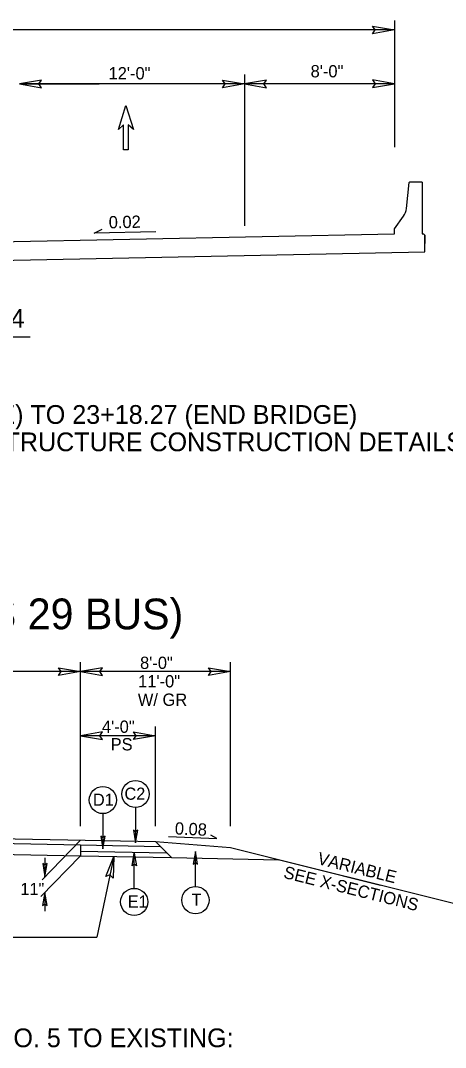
# Model space of a CAD drawing. Extents: x 1901582 to 1902252, y 193723 to 194156.
# Drawn here: x 1902055.4 to 1902078.1, y 193946 to 194000.8 of the extents above; entities that cross this region are included whole.
import ezdxf

# ---------------------------------------------------------------- set-up
doc = ezdxf.new("R2010")
doc.units = 0
for name, color, linetype in [('Old_Level_1', 7, 'Continuous'), ('Old_Level_11', 7, 'Continuous'), ('Old_Level_2', 7, 'Continuous'), ('Old_Level_20', 7, 'Continuous'), ('Prop Dimension', 7, 'Continuous'), ('Prop Dimension Text', 7, 'Continuous'), ('Typical Pavement Slope Information CELL', 7, 'Continuous'), ('Typical Terminator CELL', 7, 'Continuous'), ('Typical Text Centerline CELL', 7, 'Continuous')]:
    doc.layers.add(name, color=color, linetype=linetype)

# ---------------------------------------------------------------- blocks, each defined once
blk = doc.blocks.new('TERMINATOR')
at = {"layer": 'Typical Terminator CELL'}
blk.add_lwpolyline([(-0.469, 0.081), (0, 0), (-0.471, -0.083), (-0.411, 0)], close=True, dxfattribs=at)

msp = doc.modelspace()

# ---------------------------------------------------------------- linework, layer by layer
at = {"layer": 'Old_Level_1'}
for p, q in [((1902075.381, 194000.779), (1902075.381, 193994.021)), ((1902067.381, 193997.904), (1902067.381, 193989.821)), ((1902076.16, 193992.142), (1902076.196, 193992.179)), ((1902076.196, 193992.179), (1902076.826, 193992.179)), ((1902076.826, 193992.179), (1902076.859, 193992.146)), ((1902076.013, 193990.751), (1902076.16, 193992.142)), ((1902076.859, 193992.146), (1902076.859, 193989.398)), ((1902075.381, 193989.659), (1902075.861, 193990.344)), ((1902075.381, 193989.398), (1902075.381, 193989.659)), ((1902043.381, 193988.758), (1902075.381, 193989.398)), ((1902076.859, 193989.398), (1902076.924, 193989.398)), ((1902076.924, 193989.398), (1902076.989, 193989.333)), ((1902076.989, 193988.43), (1902076.989, 193989.333)), ((1902076.989, 193989.333), (1902076.989, 193988.876)), ((1902016.274, 193987.216), (1902076.989, 193988.43)), ((1902058.631, 193957.787), (1902058.631, 193966.537)), ((1902066.631, 193957.784), (1902066.631, 193966.537)), ((1902058.631, 193966.037), (1902046.631, 193966.037)), ((1902066.631, 193966.037), (1902058.631, 193966.037)), ((1902062.631, 193957.787), (1902062.631, 193963.118)), ((1902062.631, 193962.618), (1902058.631, 193962.618)), ((1902046.631, 193957.287), (1902062.631, 193956.967)), ((1902046.631, 193957.037), (1902058.631, 193956.797)), ((1902058.631, 193957.047), (1902056.583, 193954.931)), ((1902058.631, 193956.797), (1902058.631, 193956.213)), ((1902058.631, 193956.797), (1902062.886, 193956.712)), ((1902062.631, 193956.967), (1902063.482, 193956.116)), ((1902062.631, 193956.967), (1902066.631, 193956.647)), ((1902066.631, 193956.647), (1902074.631, 193954.647)), ((1902066.631, 193956.647), (1902078.874, 193953.586)), ((1902046.631, 193956.453), (1902058.631, 193956.213)), ((1902058.631, 193956.213), (1902056.525, 193954.037)), ((1902056.74, 193956.093), (1902056.74, 193955.093)), ((1902058.631, 193956.463), (1902063.227, 193956.372)), ((1902058.631, 193956.213), (1902063.482, 193956.116)), ((1902060.41, 193956.178), (1902059.508, 193951.867)), ((1902063.482, 193956.116), (1902069.212, 193956.002)), ((1902056.74, 193954.26), (1902056.74, 193953.26)), ((1902051.735, 193951.867), (1902059.508, 193951.867))]:
    msp.add_line(p, q, dxfattribs=at)
msp.add_arc((1902075.149, 193990.842), 0.869, 325.0087, 353.9889, dxfattribs=at)
at = {"layer": 'Old_Level_11'}
for p, q in [((1902039.318, 193983.898), (1902055.943, 193983.898)), ((1902061.569, 193958.781), (1902061.569, 193956.907)), ((1902059.829, 193958.46), (1902059.829, 193956.586)), ((1902061.498, 193954.473), (1902061.498, 193956.347)), ((1902064.765, 193954.568), (1902064.765, 193956.442))]:
    msp.add_line(p, q, dxfattribs=at)
for points in [[(1902059.713, 193957.257), (1902059.829, 193956.586), (1902059.948, 193957.261), (1902059.829, 193957.175)], [(1902061.454, 193957.579), (1902061.569, 193956.907), (1902061.689, 193957.582), (1902061.569, 193957.497)], [(1902061.383, 193955.676), (1902061.498, 193956.347), (1902061.618, 193955.672), (1902061.498, 193955.758)], [(1902064.881, 193955.77), (1902064.765, 193956.442), (1902064.646, 193955.767), (1902064.765, 193955.852)]]:
    msp.add_lwpolyline(points, close=True, dxfattribs=at)
for centre in [(1902059.829, 193959.185), (1902061.569, 193959.507), (1902061.498, 193953.748), (1902064.765, 193953.843)]:
    msp.add_circle(centre, 0.725, dxfattribs=at)
at = {"layer": 'Prop Dimension'}
msp.add_lwpolyline([(1902061.454, 193994.966), (1902061.183, 193995.216), (1902061.183, 193993.882), (1902060.933, 193993.882), (1902060.933, 193995.216), (1902060.662, 193994.966), (1902061.058, 193996.237)], close=True, dxfattribs=at)
msp.add_lwpolyline([(1902061.454, 193994.966), (1902061.183, 193995.216), (1902061.183, 193993.882), (1902060.933, 193993.882), (1902060.933, 193995.216), (1902060.662, 193994.966), (1902061.058, 193996.237)], close=True, dxfattribs=at)
at = {"layer": 'Prop Dimension Text'}
for p, q in [((1902075.381, 194000.279), (1902017.881, 194000.279)), ((1902067.381, 193997.404), (1902055.381, 193997.404)), ((1902066.631, 193997.404), (1902055.631, 193997.404)), ((1902055.631, 193997.404), (1902059.631, 193997.404)), ((1902075.381, 193997.404), (1902067.381, 193997.404))]:
    msp.add_line(p, q, dxfattribs=at)
at = {"layer": 'Typical Pavement Slope Information CELL'}
for p, q in [((1902059.372, 193989.426), (1902059.792, 193989.639)), ((1902062.646, 193989.506), (1902059.372, 193989.426)), ((1902063.326, 193957.248), (1902065.912, 193957.133)), ((1902065.912, 193957.133), (1902065.583, 193957.308))]:
    msp.add_line(p, q, dxfattribs=at)
at = {"layer": 'Typical Terminator CELL'}
for points in [[(1902074.21, 194000.481), (1902075.381, 194000.279), (1902074.203, 194000.071), (1902074.353, 194000.279)], [(1902056.553, 193997.606), (1902055.381, 193997.404), (1902056.559, 193997.196), (1902056.41, 193997.404)], [(1902066.21, 193997.606), (1902067.381, 193997.404), (1902066.203, 193997.196), (1902066.353, 193997.404)], [(1902068.553, 193997.606), (1902067.381, 193997.404), (1902068.559, 193997.196), (1902068.41, 193997.404)], [(1902074.21, 193997.202), (1902075.381, 193997.404), (1902074.203, 193997.612), (1902074.353, 193997.404)], [(1902057.46, 193966.239), (1902058.631, 193966.037), (1902057.453, 193965.829), (1902057.603, 193966.037)], [(1902059.803, 193966.239), (1902058.631, 193966.037), (1902059.809, 193965.829), (1902059.66, 193966.037)], [(1902065.46, 193966.239), (1902066.631, 193966.037), (1902065.453, 193965.829), (1902065.603, 193966.037)], [(1902059.803, 193962.82), (1902058.631, 193962.618), (1902059.809, 193962.41), (1902059.66, 193962.618)], [(1902061.46, 193962.82), (1902062.631, 193962.618), (1902061.453, 193962.41), (1902061.603, 193962.618)], [(1902059.984, 193955.102), (1902060.41, 193956.178), (1902060.373, 193955.014), (1902060.205, 193955.199)]]:
    msp.add_lwpolyline(points, close=True, dxfattribs=at)

# ---------------------------------------------------------------- block references
at = {"layer": 'Old_Level_1', "xscale": 1.5, "yscale": -1.5}
for p, rotation in [((1902056.74, 193955.093), -90), ((1902056.74, 193954.26), 90)]:
    msp.add_blockref('TERMINATOR', p, dxfattribs=dict(at, rotation=rotation))

# ---------------------------------------------------------------- texts
at = {"layer": 'Old_Level_1'}
for s, p in [('8\'-0"', (1902061.811, 193966.18)), ('11\'-0"', (1902061.709, 193965.196)), ('W/ GR', (1902061.692, 193964.212)), ('4\'-0"', (1902059.776, 193962.77))]:
    msp.add_text(s, height=0.656, dxfattribs=at).set_placement(p)
for s, p in [('VARIABLE', (1902071.227, 193955.778)), ('SEE X-SECTIONS', (1902069.419, 193955.039))]:
    msp.add_text(s, height=0.656, rotation=345.9638, dxfattribs=at).set_placement(p)
at = {"layer": 'Old_Level_11'}
for s, p in [('TYPICAL SECTION NO.  4', (1902039.528, 193984.392)), ('-L- STA 20+80.27 (BEGIN BRIDGE) TO 23+18.27 (END BRIDGE)', (1902034.08, 193979.259)), ('SEE STRUCTURE PLANS FOR STRUCTURE CONSTRUCTION DETAILS', (1902034.08, 193977.798)), ('TRANSITION FROM TYPICAL SECTION NO. 5 TO EXISTING: ', (1902029.055, 193945.997))]:
    msp.add_text(s, height=1, dxfattribs=at).set_placement(p)
at = {"layer": 'Old_Level_2'}
for s, rotation, p in [('0.02', 1.1916, (1902060.147, 193989.687)), ('0.08', 357.4644, (1902063.655, 193957.35))]:
    msp.add_text(s, height=0.656, rotation=rotation, dxfattribs=at).set_placement(p)
at = {"layer": 'Old_Level_20'}
for s, height, p in [('C2', 0.6491, (1902060.98, 193959.2)), ('D1', 0.6491, (1902059.297, 193958.879)), ('11"', 0.6491, (1902055.429, 193954.114)), ('E1', 0.6491, (1902061.153, 193953.444)), ('T', 0.649, (1902064.554, 193953.549))]:
    msp.add_text(s, height=height, dxfattribs=at).set_placement(p)
at = {"layer": 'Prop Dimension Text'}
for s, p in [('12\'-0"', (1902060.132, 193997.638)), ('8\'-0"', (1902070.905, 193997.747)), ('PS', (1902060.242, 193961.833))]:
    msp.add_text(s, height=0.656, dxfattribs=at).set_placement(p)
at = {"layer": 'Typical Text Centerline CELL'}
msp.add_text('L -L- (US 29 BUS)', height=1.64109, rotation=359.9469, dxfattribs=at).set_placement((1902046.308, 193968.308))

doc.saveas('drawing.dxf')
